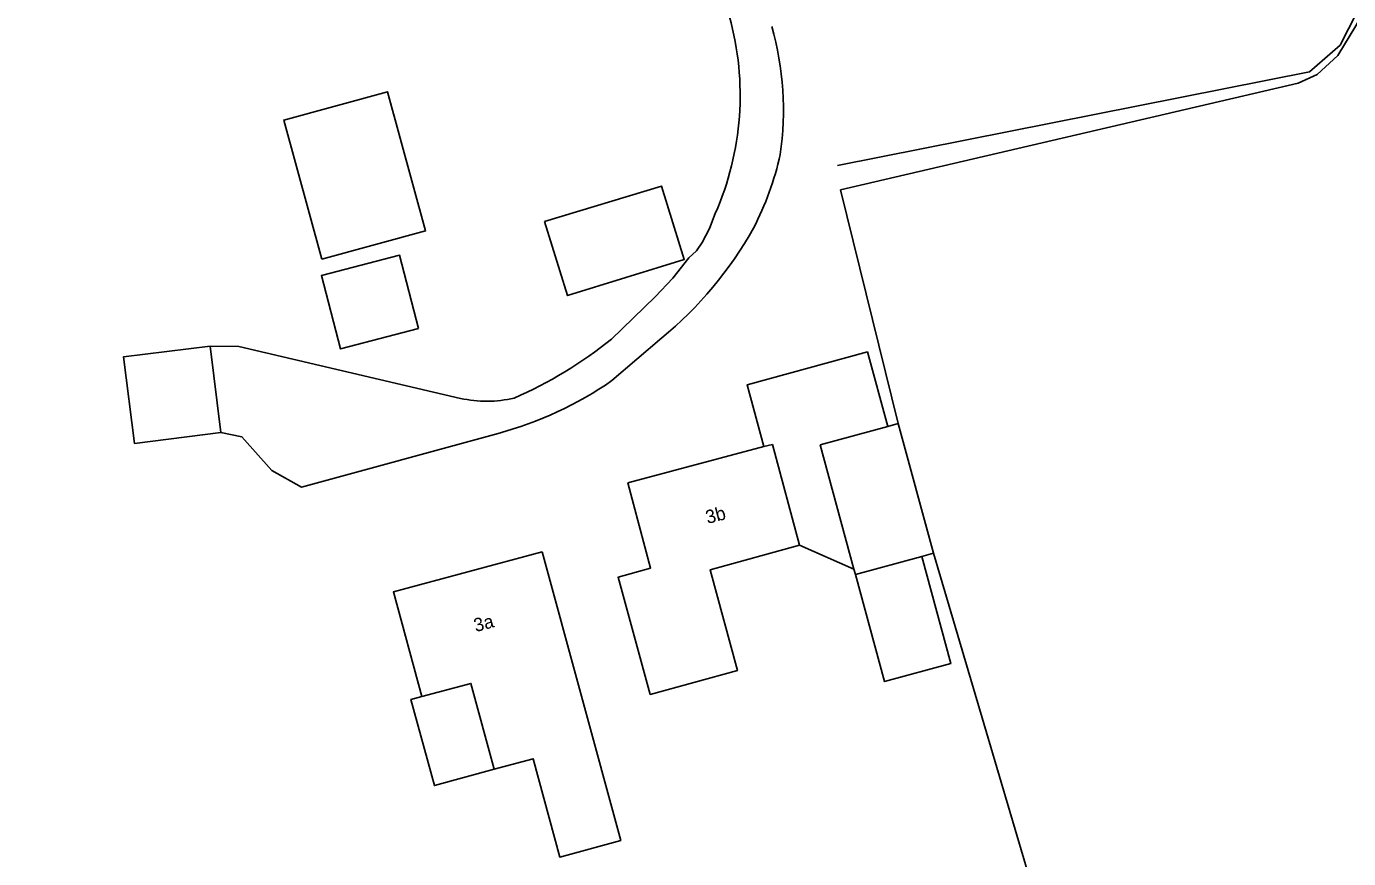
# Model space of a CAD drawing. Extents: x 135990 to 139000, y 393500 to 396000.
# Drawn here: x 137100.9 to 137199.5, y 395703.3 to 395765.4 of the extents above; entities that cross this region are included whole.
import ezdxf

# ---------------------------------------------------------------- set-up
doc = ezdxf.new("R2010")
doc.units = 0
for name, color, linetype in [('gg-anno-huisnummerreeks BGT', 7, 'Continuous'), ('gg-bbg-bijgebouw', 7, 'Continuous'), ('gg-bbg-gedigitaliseerde bebouwing', 7, 'Continuous'), ('gg-bbg-gedigitaliseerde bijgebouw', 7, 'Continuous'), ('gg-bbg-hoofdgebouw', 7, 'Continuous'), ('gg-bbg-luifel en loopbrug', 7, 'Continuous'), ('gg-knt-bronhoudergrens', 7, 'Continuous'), ('gg-knt-onverhard', 7, 'Continuous'), ('gg-kntw-midden sloot', 7, 'Continuous'), ('gt-grn-vlakafsluiter', 7, 'Continuous'), ('gx-grn-maaiveld', 7, 'Continuous')]:
    doc.layers.add(name, color=color, linetype=linetype)

msp = doc.modelspace()

# ---------------------------------------------------------------- linework, layer by layer
at = {"layer": 'gg-bbg-bijgebouw'}
for p, q in [((137160.095, 395734.173), (137165.127, 395735.546)), ((137165.127, 395735.546), (137165.903, 395735.758)), ((137165.903, 395735.758), (137168.541, 395726.091)), ((137162.611, 395724.919), (137160.095, 395734.173)), ((137167.67, 395725.853), (137162.724, 395724.504)), ((137168.541, 395726.091), (137167.67, 395725.853)), ((137162.724, 395724.504), (137162.611, 395724.919))]:
    msp.add_line(p, q, dxfattribs=at)
at = {"layer": 'gg-bbg-gedigitaliseerde bebouwing'}
msp.add_line((137158.55, 395726.685), (137156.55, 395734.211), dxfattribs=at)
msp.add_lwpolyline([(137145.75, 395731.35), (137147.453, 395724.977), (137145.025, 395724.311), (137147.421, 395715.569), (137153.926, 395717.35), (137151.888, 395724.867), (137158.55, 395726.685)], dxfattribs=at)
at = {"layer": 'gg-bbg-gedigitaliseerde bijgebouw'}
msp.add_line((137114.607, 395741.54), (137115.41, 395735.09), dxfattribs=at)
for points in [[(137139.548, 395750.836), (137141.262, 395745.307), (137149.963, 395748.005), (137148.271, 395753.461), (137139.548, 395750.836)], [(137115.41, 395735.09), (137108.96, 395734.287), (137108.157, 395740.738), (137114.607, 395741.54)]]:
    msp.add_lwpolyline(points, dxfattribs=at)
at = {"layer": 'gg-bbg-hoofdgebouw'}
for p, q in [((137155.905, 395734.04), (137145.75, 395731.35)), ((137156.55, 395734.211), (137155.905, 395734.04))]:
    msp.add_line(p, q, dxfattribs=at)
for points in [[(137139.369, 395726.211), (137128.272, 395723.21), (137130.383, 395715.403)], [(137135.783, 395709.988), (137138.697, 395710.776), (137140.68, 395703.442), (137145.219, 395704.675), (137139.369, 395726.211)], [(137130.383, 395715.403), (137134.05, 395716.395), (137135.783, 395709.988)]]:
    msp.add_lwpolyline(points, dxfattribs=at)
at = {"layer": 'gg-bbg-luifel en loopbrug'}
msp.add_line((137158.55, 395726.685), (137162.611, 395724.919), dxfattribs=at)
for points in [[(137122.929, 395748.014), (137130.669, 395750.126), (137127.841, 395760.493), (137120.1, 395758.382), (137122.929, 395748.014)], [(137130.151, 395742.844), (137128.732, 395748.31), (137122.901, 395746.795), (137124.321, 395741.329), (137130.151, 395742.844)], [(137165.127, 395735.546), (137163.612, 395741.099), (137154.646, 395738.652), (137155.905, 395734.04)], [(137167.67, 395725.853), (137169.848, 395717.871), (137164.902, 395716.522), (137162.724, 395724.504)], [(137135.783, 395709.988), (137131.326, 395708.772), (137129.577, 395715.183), (137130.383, 395715.403)]]:
    msp.add_lwpolyline(points, dxfattribs=at)
at = {"layer": 'gg-knt-bronhoudergrens'}
msp.add_lwpolyline([(137165.903, 395735.758), (137161.617, 395753.186), (137195.734, 395761.128), (137197.139, 395761.788), (137198.685, 395763.194), (137200.03, 395765.423), (137216.435, 395795.12)], dxfattribs=at)
at = {"layer": 'gg-knt-onverhard'}
for p, q in [((137116.75, 395741.502), (137133.28, 395737.642)), ((137144.569, 395738.961), (137148.28, 395742.141))]:
    msp.add_line(p, q, dxfattribs=at)
for points in [[(137144.539, 395742.059), (137147.79, 395745.2), (137149.108, 395746.601), (137150.3, 395748.11), (137150.868, 395748.632), (137151.306, 395749.267), (137151.839, 395750.316), (137152.27, 395751.411)], [(137115.41, 395735.09), (137116.98, 395734.78), (137119.2, 395732.261), (137121.42, 395731.021), (137136.08, 395735.032)]]:
    msp.add_lwpolyline(points, dxfattribs=at)
for centre, radius, start, end in [((137132.23, 395760.236), 21.897, 336.23328, 15.49616), ((137134.056, 395759.094), 23.295, 351.91733, 15.6208), ((137134.375, 395760.964), 23.319, 332.87098, 347.25503), ((137129.452, 395764.847), 29.497, 309.66625, 330.51783), ((137124.318, 395767.277), 32.324, 293.61962, 308.72421), ((137128.706, 395762.099), 28.054, 285.2393, 304.43333), ((137135.233, 395746.359), 8.933, 257.37175, 283.17406)]:
    msp.add_arc(centre, radius, start, end, dxfattribs=at)
at = {"layer": 'gg-kntw-midden sloot'}
msp.add_lwpolyline([(137161.376, 395755.003), (137196.584, 395761.988), (137198.861, 395763.962), (137214.037, 395793.722)], dxfattribs=at)
at = {"layer": 'gt-grn-vlakafsluiter'}
msp.add_line((137116.75, 395741.502), (137114.607, 395741.54), dxfattribs=at)
at = {"layer": 'gx-grn-maaiveld'}
msp.add_lwpolyline([(137168.541, 395726.091), (137185.901, 395667.412), (137060.863, 395585.12), (137104.155, 395493.558), (137084.914, 395483.606), (136995.264, 395688.299), (136962.316, 395764.268)], dxfattribs=at)

# ---------------------------------------------------------------- texts
at = {"layer": 'gg-anno-huisnummerreeks BGT'}
for s, rotation, p in [('3b', 14.8, (137151.7, 395728.272)), ('3a', 15.1, (137134.413, 395720.21))]:
    msp.add_text(s, height=1, rotation=rotation, dxfattribs=at).set_placement(p)

doc.saveas('drawing.dxf')
